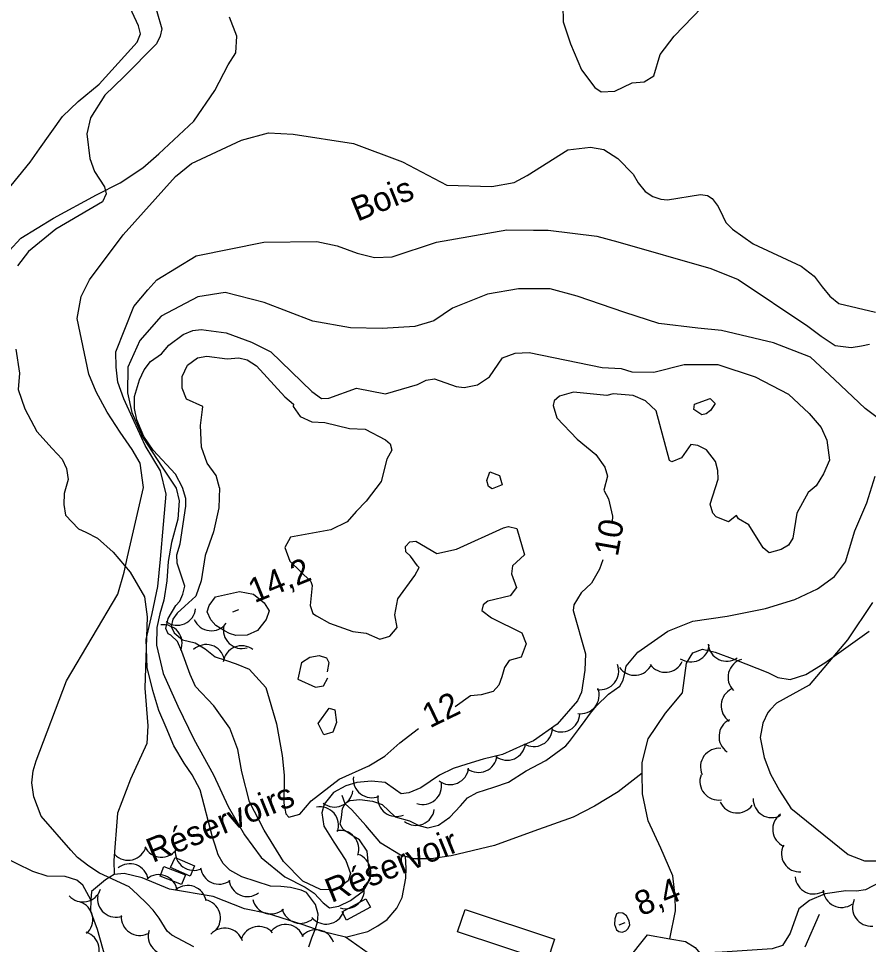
# Model space of a CAD drawing. Extents: x 362852 to 366875, y 5563573 to 5566479.
# Drawn here: x 363447.8 to 363585.1, y 5565066 to 5565215.6 of the extents above; entities that cross this region are included whole.
import ezdxf

# ---------------------------------------------------------------- set-up
doc = ezdxf.new("R2010")
doc.units = 0
for name, color, linetype in [('Niveau 1', 7, 'Continuous'), ('Niveau 2', 7, 'Continuous'), ('Niveau 22', 7, 'Continuous'), ('Niveau 3', 7, 'Continuous'), ('Niveau 31', 7, 'Continuous'), ('Niveau 33', 7, 'Continuous'), ('Niveau 37', 7, 'Continuous'), ('Niveau 44', 7, 'Continuous'), ('Niveau 52', 7, 'Continuous')]:
    doc.layers.add(name, color=color, linetype=linetype)

msp = doc.modelspace()

# ---------------------------------------------------------------- linework, layer by layer
at = {"layer": 'Niveau 1'}
for points in [[(363474.8, 5565138.07), (363474.28, 5565139.85), (363473.13, 5565142), (363469.55, 5565145.9), (363468.03, 5565148.12), (363466.92, 5565150.78), (363466.54, 5565152.61), (363466.54, 5565154.56), (363467.33, 5565157.26), (363468.1, 5565158.89), (363469.1, 5565160.22), (363470.88, 5565161.46), (363472.05, 5565162.86), (363474.36, 5565164.57), (363475.95, 5565165.21), (363477.29, 5565165.41), (363481.34, 5565164.83), (363485.45, 5565163.37), (363488.56, 5565161.8), (363495.15, 5565155.4), (363496.72, 5565154.27), (363497.93, 5565154.28), (363502.39, 5565155.91), (363507.06, 5565154.98), (363512.26, 5565156.48), (363513.62, 5565157.22), (363514.98, 5565157.43), (363518.5, 5565156.17), (363519.79, 5565156), (363521.95, 5565156.45), (363523.87, 5565157.72), (363525.97, 5565160.79), (363528.05, 5565161.55), (363530.29, 5565161.69), (363542.08, 5565159.26), (363545.13, 5565159.1), (363546.87, 5565158.53), (363550.41, 5565158.48), (363555.33, 5565159.73), (363560.77, 5565159.73), (363566.8, 5565157.76), (363572.19, 5565154.92), (363575.54, 5565151.82), (363577.44, 5565149.55), (363578.38, 5565147.53), (363578.79, 5565144.29), (363577.84, 5565142.07), (363576.65, 5565140.14), (363576.65, 5565140.14), (363575.37, 5565139.07), (363573.53, 5565135.71), (363572.91, 5565131.67), (363572.2, 5565130.56), (363570.98, 5565129.86), (363569.04, 5565129.29), (363568.09, 5565130.1), (363565.78, 5565133.84), (363564.11, 5565134.78), (363563.77, 5565135.36), (363562.48, 5565134.3), (363560.5, 5565135.13), (363559.97, 5565135.69), (363559.55, 5565137.15), (363560.84, 5565141.23), (363560.79, 5565142.63), (363560.37, 5565144.08), (363558.94, 5565145.96), (363557.53, 5565146.63), (363556.41, 5565146.82), (363554.92, 5565144.63), (363553.34, 5565144), (363552.95, 5565144.24), (363550.79, 5565152.26), (363549.09, 5565153.89), (363547.11, 5565154.71), (363543.85, 5565155), (363542.86, 5565154.71), (363537.43, 5565155.28), (363535.16, 5565154.63), (363534.32, 5565153.84), (363534.17, 5565153.1), (363534.74, 5565151.14), (363538.03, 5565147.68), (363541.05, 5565145.2)], [(363556.9, 5565152.44), (363556.98, 5565153.35), (363559.53, 5565154.24), (363560.32, 5565153.43), (363559.57, 5565152.31), (363558.86, 5565151.78), (363558.2, 5565151.58), (363556.9, 5565152.44)], [(363541.05, 5565145.2), (363542.51, 5565143.17), (363542.94, 5565141.7), (363542.36, 5565139.42), (363543.11, 5565138.04), (363543.73, 5565135.21), (363543.68, 5565134.33)], [(363474.33, 5565122.6), (363474.66, 5565123.92), (363473.43, 5565127.62), (363473.37, 5565129), (363473.92, 5565130.75), (363474.82, 5565136.83), (363474.8, 5565138.07)], [(363542.18, 5565128.18), (363541.63, 5565126.68), (363540.35, 5565124.38), (363538.69, 5565122.83), (363537.48, 5565120.9), (363537.4, 5565119.99), (363539.41, 5565112.99), (363539.3, 5565110.33), (363538.73, 5565106.79), (363538.11, 5565105.38), (363534.8, 5565101.6), (363530.99, 5565098.9), (363529.33, 5565098.23)], [(363474.15, 5565113.37), (363473.48, 5565114.95), (363472.42, 5565116), (363471.94, 5565116.24), (363471.59, 5565117.09), (363471.97, 5565118.68), (363473.2, 5565120.82), (363473.83, 5565121.52), (363474.33, 5565122.6)], [(363498.72, 5565082.57), (363500.66, 5565079.58), (363501.42, 5565077.47), (363501.04, 5565076.32), (363498.99, 5565074.83), (363496.6, 5565074.89), (363493.73, 5565076.24), (363490.59, 5565079.4), (363487.45, 5565084.5), (363485.1, 5565089.06), (363483.88, 5565093.9), (363483.22, 5565097.55), (363481.9, 5565100.98), (363479.33, 5565104.58), (363476.4, 5565107.71), (363475.52, 5565109.65), (363474.15, 5565113.37)], [(363529.33, 5565098.23), (363525.98, 5565096.69), (363522.87, 5565095.94), (363520.22, 5565095.14), (363518.01, 5565094.46), (363515.8, 5565093.35), (363512.79, 5565091.34), (363510.83, 5565090.51), (363509.58, 5565090.37), (363508.7, 5565090.99), (363507, 5565092.21), (363504.8, 5565092.41), (363502.47, 5565092.18), (363500.64, 5565091.66), (363498.66, 5565090.58), (363497.15, 5565088.7), (363496.8, 5565087.3), (363497.09, 5565085.12), (363498.72, 5565082.57)]]:
    msp.add_lwpolyline(points, dxfattribs=at)
at = {"layer": 'Niveau 2'}
for points in [[(363469.32, 5565219.63), (363470.94, 5565213.98), (363470.68, 5565212.81), (363470.08, 5565211.55), (363464.81, 5565206.21), (363461.71, 5565203.28), (363459.43, 5565199.62), (363458.84, 5565196.99), (363459.3, 5565193.05), (363460.07, 5565190.93), (363461.67, 5565188.47), (363461.96, 5565187.33), (363461.33, 5565186), (363453.84, 5565181.61), (363449.4, 5565177.99), (363447.62, 5565175.67)], [(363476.12, 5565065.63), (363472.57, 5565067.52), (363471.79, 5565068.19), (363470.53, 5565070.29), (363469.55, 5565071.57), (363468.54, 5565072.65), (363467, 5565074.07), (363465.66, 5565075.32), (363460.85, 5565077.56), (363459.13, 5565078.65), (363457.34, 5565080.09), (363456.23, 5565081.25), (363451.47, 5565086.77), (363450.28, 5565089.9), (363449.96, 5565092.14), (363450.15, 5565094.1), (363450.61, 5565095.67), (363455.55, 5565108.63), (363463.82, 5565122.61), (363464.83, 5565126.17), (363465.41, 5565128.66), (363467.96, 5565139.87), (363467.44, 5565143.79), (363466.14, 5565145.99), (363464.2, 5565148.81), (363462.09, 5565152.05), (363460.34, 5565155.33), (363459.13, 5565158.2), (363457.24, 5565167.17), (363457.89, 5565170.7), (363459.26, 5565173.4), (363464.7, 5565180.69), (363473.13, 5565190.11), (363475.75, 5565192.21), (363483.81, 5565195.97), (363488.18, 5565197.17), (363492.15, 5565196.96), (363501.93, 5565195.43), (363509.8, 5565192.48), (363517, 5565188.74), (363524.23, 5565188.51), (363527.84, 5565189.15), (363529.98, 5565190.3), (363536.51, 5565194.42), (363540.21, 5565194.85), (363542.36, 5565194.5), (363544.59, 5565193.05), (363547.11, 5565190.48), (363547.87, 5565189.11), (363549.02, 5565187.72), (363550.26, 5565186.86), (363551.55, 5565186.46), (363552.65, 5565186.36), (363557.99, 5565187.22), (363559.11, 5565187.07), (363559.83, 5565186.56), (363560.8, 5565185.28), (363561.58, 5565183.72), (363562.08, 5565182.68), (363563.15, 5565181.63), (363566.48, 5565179.21), (363574.23, 5565175.64), (363576.35, 5565174.03), (363577.63, 5565172.31), (363578.85, 5565170.76), (363580.33, 5565169.62), (363586.23, 5565168.22)], [(363494.71, 5565065.63), (363495.17, 5565067.07), (363495.72, 5565068.43), (363496.09, 5565069.64), (363496.17, 5565070.93), (363495.76, 5565072.5), (363494.33, 5565074.4), (363493.43, 5565074.77), (363491.75, 5565075.2), (363490.17, 5565075.4), (363488.52, 5565075.46), (363483.84, 5565076.94), (363481.95, 5565078.02), (363480.86, 5565079.12), (363480.02, 5565080.52), (363479.56, 5565082.07), (363479.15, 5565083.34), (363477.12, 5565090.99), (363475.84, 5565093.45), (363474.57, 5565095.29), (363472.89, 5565098.09), (363471.64, 5565101.06), (363470.48, 5565103.82), (363469.51, 5565107.04), (363468.57, 5565110.77), (363468.4, 5565115.32), (363469.4, 5565119.49), (363470.31, 5565123.87), (363470.7, 5565128.29), (363471.23, 5565133.88), (363471.66, 5565138.81), (363470.72, 5565142.54), (363468.25, 5565146.63), (363466.49, 5565150.51), (363464.82, 5565154.19), (363463.81, 5565156.89), (363463.56, 5565159.28), (363463.52, 5565161.76), (363466.43, 5565169.11), (363468.67, 5565171.8), (363470.12, 5565173.4), (363476.47, 5565177.32), (363487.41, 5565179.53), (363495.99, 5565179.63), (363499.29, 5565178.9), (363502.52, 5565177.75), (363505.32, 5565177.05), (363508.16, 5565177.12), (363515.29, 5565179.48), (363526.67, 5565181.51), (363530.96, 5565181.43), (363533.33, 5565181.43), (363541.22, 5565180.49), (363544.62, 5565179.54), (363559.66, 5565175.24), (363564.04, 5565173.45), (363575.31, 5565165.93), (363577.48, 5565164.34), (363579.75, 5565162.8), (363582.32, 5565162.5), (363583.96, 5565162.75), (363585.27, 5565163.05)], [(363588.26, 5565149.82), (363584.58, 5565152.64), (363579.63, 5565157.3), (363575.74, 5565160.91), (363569.76, 5565163.26), (363561.34, 5565165.22), (363557.55, 5565165.63), (363551.26, 5565166.35), (363545.76, 5565168.16), (363538.04, 5565170.79), (363533.69, 5565171.96), (363528.58, 5565171.94), (363523.58, 5565171.08), (363517.91, 5565168.83), (363514.89, 5565166.82), (363511.79, 5565165.89), (363506.56, 5565165.57), (363501.41, 5565165.65), (363495.35, 5565166.73), (363487.46, 5565169.78), (363481.17, 5565171.38), (363476.74, 5565170.65), (363470.81, 5565167.54), (363467.36, 5565163.59), (363465.42, 5565159.29), (363465.41, 5565155.16), (363466.09, 5565151.98), (363467.86, 5565147.92), (363470.99, 5565143.13), (363473.27, 5565139.78), (363473.76, 5565137.73), (363473.51, 5565134.76), (363472.49, 5565130.96), (363471.95, 5565127.93), (363471.77, 5565124.8), (363471.28, 5565121.66), (363470.59, 5565119.44), (363470.14, 5565117.25), (363470.1, 5565114.37), (363471.14, 5565109.81), (363473.5, 5565104.5), (363476.11, 5565099.17), (363479.26, 5565093.44), (363481.66, 5565088.33), (363484.27, 5565083.75), (363486.99, 5565080.09), (363490.81, 5565076.95), (363494.07, 5565075.26), (363495.53, 5565074.32), (363497, 5565072.75), (363498.03, 5565071.93), (363499.54, 5565072.19), (363501.4, 5565073.1), (363503.54, 5565074.68)], [(363480.27, 5565139.82), (363479.7, 5565141.78), (363478.24, 5565143.82), (363477.34, 5565146.38), (363477.2, 5565149.89), (363477.52, 5565152.44), (363477.54, 5565152.96), (363474.9, 5565154.14), (363474.24, 5565155.89), (363474.21, 5565157.81), (363475.09, 5565159.65), (363476.69, 5565160.84), (363478.19, 5565161.1), (363481.49, 5565160.63), (363483.37, 5565160.81), (363484.7, 5565160.51), (363486.21, 5565159.53), (363490.83, 5565154.5), (363492.23, 5565153.33), (363492.15, 5565152.94), (363493.31, 5565151.36), (363495.15, 5565150.46), (363497.29, 5565150.38), (363501.28, 5565149.41), (363503.79, 5565149.27), (363507.1, 5565147.57), (363507.81, 5565146.9), (363508.09, 5565145.92), (363507.28, 5565144.44), (363506.38, 5565140.84), (363503.96, 5565137.67), (363502.35, 5565135.97), (363500.89, 5565134.32), (363498.25, 5565133.04), (363491.74, 5565131.84), (363490.82, 5565130.18), (363491.63, 5565127.94), (363495.03, 5565124.69), (363495.22, 5565124.02), (363494.93, 5565120.77), (363495.31, 5565119.48), (363495.95, 5565119.14), (363498.04, 5565117.96), (363501.78, 5565116.58), (363503.97, 5565116.33), (363506.17, 5565115.38), (363507.79, 5565115.86), (363508.97, 5565117.25), (363508.56, 5565119.26), (363509.05, 5565121.85), (363511.84, 5565125.64), (363512.51, 5565126.91), (363512.26, 5565127.2), (363511.1, 5565128.79), (363510.38, 5565129.47), (363510.29, 5565130.33), (363510.98, 5565131.06), (363511.99, 5565131.17), (363515.38, 5565129.17), (363518.54, 5565129.88), (363526.15, 5565133.32), (363526.96, 5565133.56), (363528.28, 5565133.24)], [(363523.71, 5565140.03), (363523.43, 5565141), (363523.91, 5565142.37), (363525.47, 5565141.78), (363525.9, 5565140.31), (363524.33, 5565139.66), (363523.71, 5565140.03)], [(363545.95, 5565110.98), (363547.86, 5565113.27), (363552.67, 5565116.67), (363556.74, 5565118.25), (363562.26, 5565119.07), (363568.48, 5565120.3), (363573.21, 5565121.79), (363576.88, 5565123.46), (363579.64, 5565125.49), (363581.4, 5565127.85), (363582.91, 5565132.85), (363584.86, 5565137.41), (363586.18, 5565141.71)], [(363480.27, 5565139.82), (363480.17, 5565136.55), (363479.3, 5565132.71), (363477.92, 5565128.89), (363477.29, 5565124.77), (363476.45, 5565122.31)], [(363528.28, 5565133.24), (363529.51, 5565129), (363527.57, 5565127.21), (363527.42, 5565125.92), (363528.23, 5565123.69), (363527.22, 5565122.33), (363523.6, 5565121.47), (363522.87, 5565120.92), (363522.62, 5565119.97), (363524.18, 5565118.82), (363529.12, 5565116.36), (363529.8, 5565114.62), (363529.02, 5565112.44), (363527.06, 5565111.88), (363526.32, 5565110.8), (363525.88, 5565109.27), (363525.41, 5565107.9), (363524.46, 5565106.92), (363522.51, 5565106.34), (363520.79, 5565106.21), (363518.31, 5565104.43)], [(363481.06, 5565116.72), (363479.65, 5565117.56), (363478.84, 5565118.46), (363478.28, 5565119.78), (363478.6, 5565120.79), (363479.62, 5565122.21), (363483.48, 5565123.08), (363485.73, 5565122.6), (363487.48, 5565121.22), (363488.27, 5565119.94), (363487.82, 5565118.51), (363486.39, 5565116.73), (363484.7, 5565116.02), (363482.88, 5565115.94), (363481.87, 5565116.26), (363481.06, 5565116.72)], [(363476.45, 5565122.31), (363474.65, 5565120.68), (363473.41, 5565119.57), (363472.7, 5565118.59), (363472.45, 5565117.42), (363472.94, 5565116.39), (363474.28, 5565115.27), (363476.3, 5565114.75), (363477.96, 5565113.77), (363479.55, 5565112.51), (363481.21, 5565111.96), (363482.94, 5565111.38)], [(363585.76, 5565121.27), (363581.73, 5565115.27), (363575.51, 5565107.91), (363570.24, 5565105.01)], [(363493.53, 5565111.57), (363494.86, 5565112.46), (363496.37, 5565112.71), (363497.55, 5565112.36), (363497.94, 5565111.58), (363497.66, 5565110.1)], [(363482.94, 5565111.38), (363485.03, 5565110.48), (363487.76, 5565107.53), (363489.48, 5565101.66), (363490.38, 5565096.56), (363490.73, 5565093.35), (363490.64, 5565088.83), (363490.99, 5565087.11), (363491.47, 5565086.57), (363493.25, 5565087.07), (363495.08, 5565089.21), (363499.58, 5565092.71), (363504.4, 5565094.86), (363506.97, 5565096.43), (363509.38, 5565098.6), (363512.39, 5565100.91)], [(363493.53, 5565111.57), (363492.92, 5565108.89), (363495.75, 5565107.61), (363497.08, 5565107.82), (363497.78, 5565109.08)], [(363503.54, 5565074.68), (363504.63, 5565076.7), (363504.34, 5565078.88), (363504.1, 5565081.09), (363502.88, 5565082.95), (363501.83, 5565083.51), (363500.87, 5565084.17), (363500.25, 5565084.6), (363499.77, 5565085.45), (363499.94, 5565086.52), (363500.14, 5565087.98), (363500.59, 5565088.85), (363501.34, 5565089.29), (363502.95, 5565089.47), (363504.99, 5565089.2), (363506.55, 5565088.61), (363508.61, 5565086.67), (363510.94, 5565086.02), (363512.46, 5565085.23), (363513.93, 5565084.84), (363515.66, 5565085.32), (363517.45, 5565086.57), (363519.17, 5565088.41), (363520.31, 5565089.7), (363521.89, 5565090.55), (363524.57, 5565091.43), (363526.97, 5565092.25), (363529.82, 5565094.07), (363533, 5565095.72), (363536.23, 5565098.13), (363536.81, 5565098.81), (363538.25, 5565100.73), (363539.31, 5565102.23), (363540.18, 5565103.41), (363541.14, 5565104.56), (363543.09, 5565106.44), (363544.96, 5565107.78), (363545.48, 5565108.75), (363545.76, 5565109.87), (363545.95, 5565110.98)], [(363497.1, 5565099.89), (363496.21, 5565101.73), (363497.96, 5565104.18), (363498.91, 5565103.94), (363499.16, 5565101.88), (363498.56, 5565100.3), (363497.1, 5565099.89)], [(363570.24, 5565105.01), (363569.24, 5565103.96), (363568.87, 5565103.5), (363568.04, 5565101.77), (363567.63, 5565099.48), (363568.24, 5565096.23), (363569.25, 5565093.53), (363570.73, 5565090.9), (363572.55, 5565088.05), (363581.81, 5565080.56), (363584.48, 5565079.56), (363586.75, 5565079.51)], [(363544.42, 5565070.97), (363544.14, 5565070.16), (363544.08, 5565069.27), (363544.38, 5565068.4), (363544.75, 5565068.11), (363545.29, 5565068.03), (363545.89, 5565068.22), (363546.25, 5565068.56), (363546.57, 5565069.13), (363546.46, 5565069.83), (363546, 5565070.63), (363545.44, 5565071.08), (363544.79, 5565071.13), (363544.42, 5565070.97)]]:
    msp.add_lwpolyline(points, dxfattribs=at)
at = {"layer": 'Niveau 22'}
for points in [[(363443.97, 5565185.46), (363449.65, 5565192.45), (363451.19, 5565194.6), (363454.87, 5565199.81), (363457.41, 5565202.26), (363460.8, 5565205.02), (363466.97, 5565211.83), (363467.47, 5565213.17), (363467.17, 5565214.49), (363464.81, 5565219.63)], [(363535.7, 5565217.82), (363535.78, 5565215.1), (363536.97, 5565211.54), (363538.74, 5565207.34), (363540.88, 5565204.48), (363541.92, 5565203.79), (363544.12, 5565203.9), (363546.93, 5565205.25), (363548.85, 5565205.41), (363550.44, 5565206.37), (363551.45, 5565209.82), (363553.71, 5565212.79), (363559.67, 5565219.05)], [(363446.26, 5565178.08), (363448.15, 5565180.13), (363453.41, 5565183.37), (363460.39, 5565187.18), (363464.23, 5565189.11), (363467.87, 5565191.53), (363470.47, 5565193.78), (363476.12, 5565199.08), (363479.51, 5565204.02), (363481.68, 5565208.16), (363482.92, 5565210.11), (363483.04, 5565212.79), (363481.87, 5565215.85)], [(363447.34, 5565162.19), (363447.96, 5565158.32), (363447.74, 5565155.72), (363448.79, 5565152.56), (363450.74, 5565148.9), (363453.2, 5565146.16), (363454.83, 5565144.44), (363455.54, 5565142.92), (363455.78, 5565141.15), (363455.17, 5565138.89), (363455.1, 5565137.11), (363455.38, 5565135.41), (363457.5, 5565133.17), (363458.66, 5565132.65), (363460.56, 5565131.69), (363463.07, 5565129.43), (363465.81, 5565126.19), (363468.14, 5565122.21), (363468.59, 5565118.98), (363468.18, 5565107.41), (363468.68, 5565101.33), (363468.5, 5565098.5), (363465.88, 5565092.73), (363463.78, 5565087.25), (363463.16, 5565079.59), (363463.23, 5565077.35)], [(363553.02, 5565066.93), (363553.93, 5565071.48), (363553.86, 5565073.85), (363553.48, 5565077.13), (363551.58, 5565081.59), (363549.52, 5565086.01), (363548.57, 5565090.38), (363548.54, 5565093.7), (363548.52, 5565095.41), (363549.52, 5565099.27), (363552.29, 5565103.37), (363555.04, 5565106.68), (363555.7, 5565111.46), (363556.74, 5565113.15), (363558.3, 5565113.72), (363560.36, 5565113.27), (363563.54, 5565112.08), (363568.82, 5565109.96), (363570.44, 5565109.15), (363572.46, 5565108.81), (363574.99, 5565109.63), (363578.06, 5565111.52), (363585.21, 5565116.62)], [(363548.54, 5565093.7), (363544.64, 5565090.67), (363540.86, 5565088.39), (363537.39, 5565086.58), (363531.05, 5565084.35), (363524.68, 5565081.99), (363517.69, 5565080.36), (363514.45, 5565079.83), (363511.68, 5565079.83), (363510.32, 5565080.23), (363509.48, 5565080.47), (363506.3, 5565082.38), (363503.9, 5565085.25), (363501.66, 5565087.75), (363500.55, 5565088.75), (363500.07, 5565090.09)], [(363459.49, 5565073.24), (363458.16, 5565075.61), (363457.22, 5565076.42), (363455.34, 5565077.01), (363452.42, 5565077.06), (363450.11, 5565077.79), (363444.74, 5565080.42)], [(363500.63, 5565067.21), (363504.21, 5565068.14), (363505.84, 5565069.04), (363507.36, 5565070.07), (363508.88, 5565071.86), (363509.77, 5565073.61), (363510.34, 5565076.74), (363510.42, 5565078.34), (363510.32, 5565080.23)], [(363504.26, 5565064.6), (363500.63, 5565067.21), (363496.84, 5565068.13), (363493.59, 5565069.27), (363488.03, 5565071.03), (363484.3, 5565071.79), (363479.21, 5565073.78), (363472.17, 5565074.97), (363467.75, 5565076.79), (363464.87, 5565077.5), (363463.23, 5565077.35), (363461.85, 5565076.46), (363459.6, 5565074.58), (363459.49, 5565073.24), (363459.44, 5565071.38), (363460.51, 5565068.48), (363462.2, 5565062.36)], [(363587.02, 5565076.1), (363584.64, 5565074.87), (363583.15, 5565074.61), (363581.45, 5565074.69), (363578.11, 5565074.19), (363575.59, 5565073.1), (363573.85, 5565071.77), (363572.48, 5565067.87), (363571.21, 5565065.84), (363569.53, 5565065.3), (363561.47, 5565064.75), (363557.85, 5565064.63)]]:
    msp.add_lwpolyline(points, dxfattribs=at)
at = {"layer": 'Niveau 3'}
for p, q in [((363482.39, 5565119.78), (363483.37, 5565120.17)), ((363544.82, 5565069.19), (363545.78, 5565069.58))]:
    msp.add_line(p, q, dxfattribs=at)
at = {"layer": 'Niveau 31'}
msp.add_lwpolyline([(363533.17, 5565063.26), (363518.73, 5565068.06), (363519.92, 5565071.65), (363534.36, 5565066.85), (363533.17, 5565063.26)], dxfattribs=at)
at = {"layer": 'Niveau 33'}
for points in [[(363473.07, 5565080.09), (363476.21, 5565078.72), (363475.5, 5565077.08), (363472.36, 5565078.45), (363473.07, 5565080.09)], [(363471.25, 5565078.61), (363474.74, 5565077.27), (363474.14, 5565075.71), (363470.65, 5565077.05), (363471.25, 5565078.61)], [(363504.64, 5565072.05), (363500.8, 5565069.92), (363500.05, 5565071.28), (363503.89, 5565073.41), (363504.64, 5565072.05)]]:
    msp.add_lwpolyline(points, dxfattribs=at)
at = {"layer": 'Niveau 37'}
msp.add_line((363574.85, 5565065.64), (363577.18, 5565070.89), dxfattribs=at)
at = {"layer": 'Niveau 44'}
for centre, start, end in [((363473.41, 5565120.6), 233.7319, 353.7098), ((363478.93, 5565119.71), 203.5345, 323.5125), ((363471.21, 5565114.69), 338.4968, 98.4747), ((363483.88, 5565116.84), 166.3394, 286.3174), ((363478.11, 5565111.48), 12.7998, 132.7778), ((363483.85, 5565111.29), 52.7864, 172.7643), ((363556.4, 5565114.67), 235.6121, 355.59), ((363562.21, 5565114.79), 184.6824, 304.6604), ((363541.75, 5565110.19), 261.0399, 21.0178), ((363547.32, 5565112.52), 215.546, 335.524), ((363552.3, 5565113), 215.546, 335.524), ((363565.41, 5565109.19), 105.3398, 225.3178), ((363538.6, 5565106.31), 261.0399, 21.0178), ((363564.29, 5565104.61), 116.0861, 236.064), ((363535.46, 5565103.36), 238.0315, 358.0095), ((363563.95, 5565099.63), 116.0861, 236.064), ((363531.05, 5565101.01), 238.0315, 358.0095), ((363526.71, 5565098.79), 233.2199, 353.1979), ((363560.96, 5565094.72), 84.0445, 204.0224), ((363522.11, 5565096.82), 233.2199, 353.1979), ((363504.86, 5565092.74), 172.6339, 292.6118), ((363517.52, 5565094.85), 233.2199, 353.1979), ((363560.87, 5565092.36), 159.2198, 279.1977), ((363513.15, 5565091.65), 250.7849, 10.7629), ((363498.84, 5565091.23), 232.3713, 352.3493), ((363508.83, 5565089.7), 172.6339, 292.6118), ((363563.88, 5565090.27), 204.6753, 324.6532), ((363569.48, 5565089.52), 178.6615, 298.6394), ((363496.49, 5565085.25), 340.7966, 100.7745), ((363511.99, 5565088.26), 232.2389, 352.2169), ((363572.63, 5565084.64), 125.9876, 245.9655), ((363499.76, 5565081.46), 340.7966, 100.7745), ((363465.49, 5565082.63), 224.2142, 344.1922), ((363470.88, 5565083.12), 206.1237, 326.1016), ((363476.1, 5565080.99), 174.3497, 294.3277), ((363574.03, 5565080.73), 153.2327, 273.2106), ((363501.69, 5565077.73), 311.4678, 71.4457), ((363465.77, 5565076.06), 9.4706, 129.4485), ((363480.19, 5565078.76), 186.3345, 306.3125), ((363470.45, 5565074.31), 9.4706, 129.4485), ((363576.25, 5565077.17), 184.4517, 304.4296), ((363475.13, 5565072.55), 9.4706, 129.4485), ((363484.77, 5565076.76), 186.3345, 306.3125), ((363500.65, 5565074.8), 252.7373, 12.7152), ((363458.19, 5565075.88), 221.5219, 341.4999), ((363463.55, 5565073.41), 169.4996, 289.4776), ((363580.76, 5565075.01), 184.4517, 304.4296), ((363456.78, 5565070.03), 311.7572, 71.7352), ((363477.4, 5565070.29), 318.118, 78.0959), ((363488.56, 5565073.94), 192.4099, 312.3878), ((363585.53, 5565071.99), 154.9624, 274.9403), ((363467.38, 5565070.47), 175.7345, 295.7124), ((363493.33, 5565072.43), 192.4099, 312.3878), ((363497.47, 5565072.31), 219.9694, 339.9474), ((363490.94, 5565066.26), 19.8017, 139.7797), ((363457.8, 5565065.14), 311.7572, 71.7352), ((363471.74, 5565067.38), 162.3044, 282.2824), ((363481.1, 5565065.67), 18.4462, 138.4241), ((363486.6, 5565065.93), 41.5775, 161.5554), ((363495.86, 5565065.38), 19.8017, 139.7797)]:
    msp.add_arc(centre, 3, start, end, dxfattribs=at)
at = {"layer": 'Niveau 52'}
msp.add_lwpolyline([(363540.73, 5565041.1), (363540.11, 5565042.92), (363537.22, 5565045.66), (363532.57, 5565048.68), (363524.4, 5565051.9), (363518.67, 5565054.32), (363519.15, 5565054.97), (363520.83, 5565057.25), (363525.87, 5565055.49), (363527.27, 5565056.33), (363532.66, 5565054.37), (363537.66, 5565053.5), (363539.3, 5565054.19), (363540.8, 5565056.13), (363542.69, 5565059.35), (363546.02, 5565063.31), (363549.42, 5565067.55), (363553.02, 5565066.93), (363555.54, 5565066.49), (363557.13, 5565065.54), (363557.85, 5565064.63), (363559.15, 5565062.98), (363561.09, 5565062.1)], dxfattribs=at)

# ---------------------------------------------------------------- texts
at = {"layer": 'Niveau 1'}
msp.add_text('10', height=3.93, rotation=79.9993, dxfattribs=at).set_placement((363544.61, 5565128.59))
at = {"layer": 'Niveau 2'}
msp.add_text('12', height=3.93, rotation=25.9442, dxfattribs=at).set_placement((363514.24, 5565100.92))
at = {"layer": 'Niveau 3'}
for s, p in [('14,2 ', (363485.91, 5565121.15)), ('8,4  ', (363548.33, 5565070.55))]:
    msp.add_text(s, height=3.93, rotation=22.09, dxfattribs=at).set_placement(p)
at = {"layer": 'Niveau 33'}
for s, p in [('Réservoirs', (363469.46, 5565079.18)), ('Réservoir', (363498.33, 5565072.71))]:
    msp.add_text(s, height=3.93, rotation=22.09, dxfattribs=at).set_placement(p)
at = {"layer": 'Niveau 44'}
msp.add_text('Bois', height=3.93, rotation=22.09, dxfattribs=at).set_placement((363502.54, 5565182.79))

doc.saveas('drawing.dxf')
